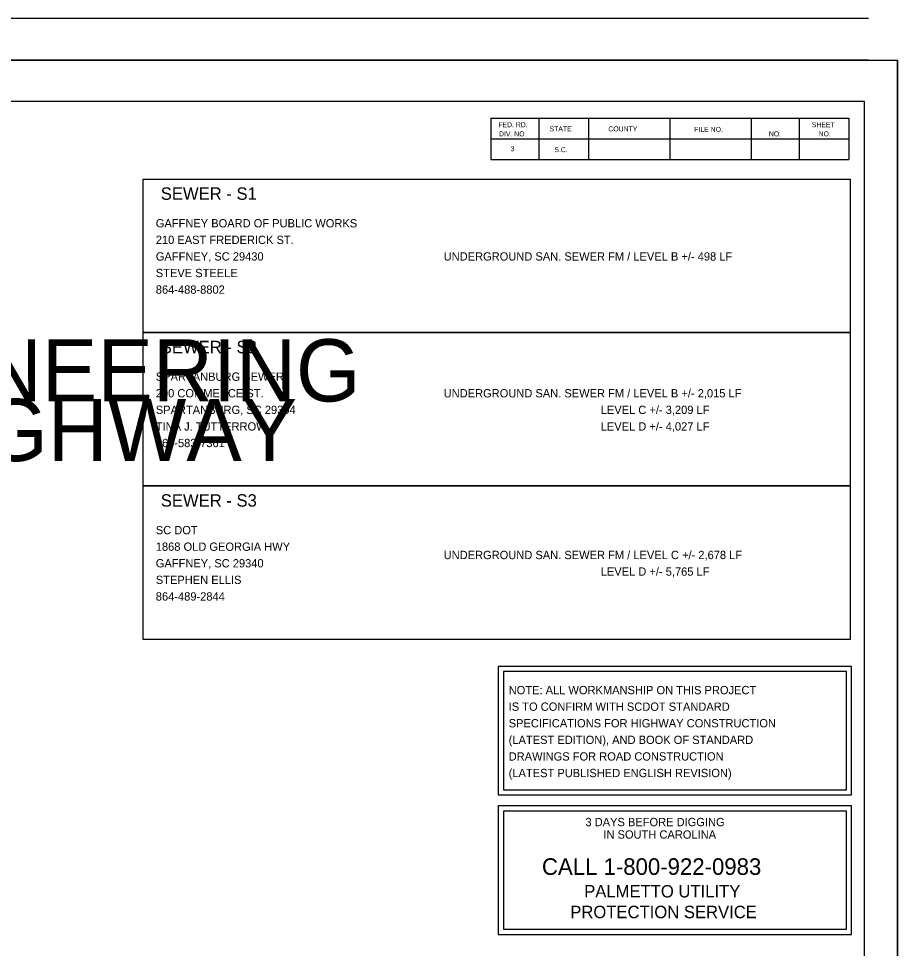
# Model space of a CAD drawing. Extents: x 189971 to 191767, y 195697 to 196847.
# Drawn here: x 191237 to 191767, y 196286 to 196847 of the extents above; entities that cross this region are included whole.
import ezdxf

# ---------------------------------------------------------------- set-up
doc = ezdxf.new("R2010")
doc.units = 0
for name, color, linetype in [('Default', 7, 'Continuous'), ('RD_SHT_Bndy', 7, 'Continuous'), ('RD_SHT_Iplotshp', 7, 'Continuous'), ('RD_SHT_Snap', 7, 'Continuous'), ('RD_SHT_TX', 7, 'Continuous')]:
    doc.layers.add(name, color=color, linetype=linetype)

msp = doc.modelspace()

# ---------------------------------------------------------------- linework, layer by layer
at = {"layer": 'RD_SHT_Bndy'}
for p, q in [((191749.96, 196847.12), (189989.96, 196847.12)), ((191749.96, 196822.12), (189989.96, 196822.12)), ((191747.56, 196797.12), (190072.56, 196797.12)), ((191747.56, 195747.12), (191747.56, 196797.12)), ((191522.06, 196787.12), (191522.06, 196762.12)), ((191522.06, 196787.12), (191679.06, 196787.12)), ((191551.06, 196787.12), (191551.06, 196762.12)), ((191581.06, 196787.12), (191581.06, 196762.12)), ((191630.06, 196787.12), (191630.06, 196762.12)), ((191679.06, 196787.12), (191679.06, 196762.12)), ((191679.06, 196787.12), (191738.06, 196787.12)), ((191708.06, 196787.12), (191708.06, 196762.12)), ((191738.06, 196787.12), (191738.06, 196762.12)), ((191522.06, 196774.62), (191679.06, 196774.62)), ((191679.06, 196774.62), (191738.06, 196774.62)), ((191522.06, 196762.12), (191679.06, 196762.12)), ((191679.06, 196762.12), (191738.06, 196762.12))]:
    msp.add_line(p, q, dxfattribs=at)
for points in [[(191312.43, 196750.34), (191738.9, 196750.34), (191738.9, 196657.83), (191312.43, 196657.83)], [(191312.43, 196657.83), (191738.9, 196657.83), (191738.9, 196565.33), (191312.43, 196565.33)], [(191312.43, 196565.33), (191738.9, 196565.33), (191738.9, 196472.82), (191312.43, 196472.82)], [(191526.6, 196379.07), (191739.67, 196379.07), (191739.67, 196456.5), (191526.6, 196456.5)], [(191529.69, 196382.16), (191736.58, 196382.16), (191736.58, 196453.41), (191529.69, 196453.41)], [(191526.6, 196294.94), (191739.67, 196294.94), (191739.67, 196372.37), (191526.6, 196372.37)], [(191529.69, 196298.04), (191736.58, 196298.04), (191736.58, 196369.28), (191529.69, 196369.28)]]:
    msp.add_lwpolyline(points, close=True, dxfattribs=at)
at = {"layer": 'RD_SHT_Iplotshp'}
msp.add_lwpolyline([(189971.36, 196822.12), (191767.36, 196822.12), (191767.36, 195722.12), (189971.36, 195722.12)], close=True, dxfattribs=at)
at = {"layer": 'RD_SHT_Snap'}
msp.add_line((191767.36, 195722.12), (191767.36, 196822.12), dxfattribs=at)

# ---------------------------------------------------------------- texts
at = {"layer": 'Default'}
for s, p in [('SUBSURFACE UTILITY ENGINEERING', (190535.21, 196616.27)), ('FOR PROPOSED STATE HIGHWAY', (190572.24, 196580.32))]:
    msp.add_text(s, height=37.5, dxfattribs=at).set_placement(p)
at = {"layer": 'RD_SHT_TX'}
for s, height, p in [('FED. RD.', 3, (191526.61, 196781.62)), ('SHEET', 3, (191715.71, 196781.62)), ('DIV. NO.', 3, (191527.01, 196776.12)), ('STATE', 3, (191557.51, 196779.12)), ('COUNTY', 3, (191593.01, 196779.12)), ('FILE NO.', 3, (191644.8, 196778.82)), ('NO.', 3, (191689.81, 196776.12)), ('NO.', 3, (191719.86, 196776.12)), ('3', 3, (191534.06, 196767.12)), ('S.C.', 3, (191560.4, 196766.59)), ('SEWER - S1', 7.5, (191322.99, 196737.85)), ('GAFFNEY BOARD OF PUBLIC WORKS', 5, (191319.99, 196721.22)), ('210 EAST FREDERICK ST.', 5, (191319.99, 196711.22)), ('GAFFNEY, SC 29430', 5, (191319.99, 196701.22)), ('UNDERGROUND SAN. SEWER FM / LEVEL B +/- 498 LF', 5, (191493.64, 196701.22)), ('STEVE STEELE', 5, (191319.99, 196691.22)), ('864-488-8802', 5, (191319.99, 196681.22)), ('SEWER - S2', 7.5, (191322.99, 196645.34)), ('SPARTANBURG SEWER', 5, (191319.99, 196628.72)), ('200 COMMERCE ST.', 5, (191319.99, 196618.72)), ('UNDERGROUND SAN. SEWER FM / LEVEL B +/- 2,015 LF', 5, (191493.64, 196618.72)), ('SPARTANBURG, SC 29304', 5, (191319.99, 196608.72)), ('                                                   LEVEL C +/- 3,209 LF', 5, (191493.64, 196608.72)), ('TINA J. TUTTERROW', 5, (191319.99, 196598.72)), ('                                                   LEVEL D +/- 4,027 LF', 5, (191493.64, 196598.72)), ('864-583-7361', 5, (191319.99, 196588.72)), ('SEWER - S3', 7.5, (191322.99, 196552.84)), ('SC DOT', 5, (191319.99, 196536.21)), ('1868 OLD GEORGIA HWY', 5, (191319.99, 196526.21)), ('UNDERGROUND SAN. SEWER FM / LEVEL C +/- 2,678 LF                ', 5, (191493.64, 196521.21)), ('GAFFNEY, SC 29340', 5, (191319.99, 196516.21)), ('                                                   LEVEL D +/- 5,765 LF', 5, (191493.64, 196511.21)), ('STEPHEN ELLIS', 5, (191319.99, 196506.21)), ('864-489-2844', 5, (191319.99, 196496.21)), ('NOTE: ALL WORKMANSHIP ON THIS PROJECT', 5, (191532.87, 196439.75)), ('IS TO CONFIRM WITH SCDOT STANDARD', 5, (191532.87, 196429.75)), ('SPECIFICATIONS FOR HIGHWAY CONSTRUCTION', 5, (191532.87, 196419.75)), ('(LATEST EDITION), AND BOOK OF STANDARD ', 5, (191532.87, 196409.75)), ('DRAWINGS FOR ROAD CONSTRUCTION ', 5, (191532.87, 196399.75)), ('(LATEST PUBLISHED ENGLISH REVISION)', 5, (191532.87, 196389.75)), ('3 DAYS BEFORE DIGGING', 5, (191579.17, 196360.18)), ('IN SOUTH CAROLINA', 5, (191589.99, 196352.68)), ('CALL 1-800-922-0983', 10, (191552.92, 196330.83)), ('PALMETTO UTILITY', 7.5, (191578.42, 196317.21)), ('PROTECTION SERVICE', 7.5, (191570.01, 196304.71))]:
    msp.add_text(s, height=height, dxfattribs=at).set_placement(p)

doc.saveas('drawing.dxf')
